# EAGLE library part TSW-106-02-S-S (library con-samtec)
THROUGH-HOLE .025" SQ POST HEADER Source: Samtec TSW.pdf
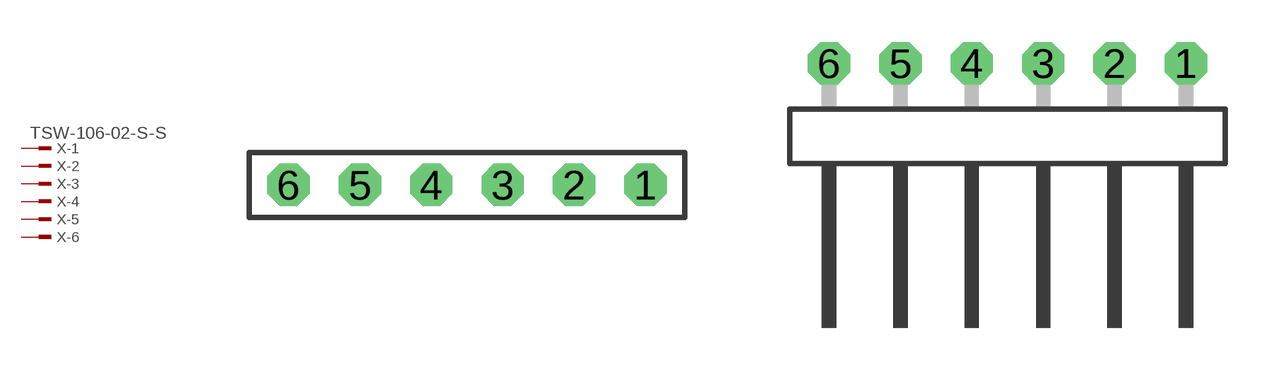
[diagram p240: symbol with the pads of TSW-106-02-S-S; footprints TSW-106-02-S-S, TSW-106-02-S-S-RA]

Designator prefix X; gates -1=MPINV -2=MPIN -3=MPIN -4=MPIN -5=MPIN -6=MPIN

## TSW-106-02-S-S (OC_FARNELL: unknown; OC_NEWARK: unknown)  [TSW-106-02-S-S]
1  -1:1  pas
2  -2:1  pas
3  -3:1  pas
4  -4:1  pas
5  -5:1  pas
6  -6:1  pas

## TSW-106-02-S-S-RA (OC_FARNELL: unknown; OC_NEWARK: unknown)  [TSW-106-02-S-S-RA]
Pads as for TSW-106-02-S-S

## Footprint TSW-106-02-S-S (pad centres in mm)
THROUGH-HOLE .025" SQ POST HEADER Source: Samtec TSW.pdf
drill 1 pad 1.5 octagon: 1 6.35,0; 2 3.81,0; 3 1.27,0; 4 -1.27,0; 5 -3.81,0; 6 -6.35,0

## Footprint TSW-106-02-S-S-RA (pad centres in mm)
THROUGH-HOLE .025" SQ POST HEADER Source: Samtec TSW.pdf
drill 1 pad 1.5 octagon: 1 6.35,1.524; 2 3.81,1.524; 3 1.27,1.524; 4 -1.27,1.524; 5 -3.81,1.524; 6 -6.35,1.524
